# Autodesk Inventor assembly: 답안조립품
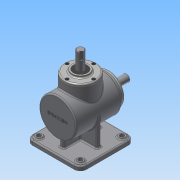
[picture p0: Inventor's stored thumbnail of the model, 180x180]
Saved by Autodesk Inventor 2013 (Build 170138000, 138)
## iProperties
Created: 2015-07
Part Number: 답안조립품
Document SubType Name: Assembly
Designer: Administrator
Author: Administrator
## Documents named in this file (14)
- C:\Users\Administrator\Desktop\450706V1016\답안조립품.iam
- C:\Users\Administrator\Desktop\450706V1016\본체.ipt
- C:\Users\Administrator\Desktop\450706V1016\M4.ipt
- C:\Users\Administrator\Desktop\450706V1016\메인 베벨기어.ipt
- C:\Users\Administrator\Desktop\450706V1016\메인 축.ipt
- 메인 축.ipt
- C:\Users\Administrator\Desktop\450706V1016\베어링 6203.ipt
- C:\Users\Administrator\Desktop\450706V1016\서브 베벨기어.ipt
- C:\Users\Administrator\Desktop\450706V1016\서브 축.ipt
- 서브 축.ipt
- C:\Users\Administrator\Desktop\450706V1016\오일실.ipt
- C:\Users\Administrator\Desktop\450706V1016\커버.ipt
- C:\Users\Administrator\Desktop\450706V1016\키 4x4.ipt
- C:\Users\Administrator\Desktop\450706V1016\키 5x5.ipt
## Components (8 placed, 1 different names)
1. M4:2
2. M4:3
3. M4:4
4. M4:5
5. M4:1
6. M4:6
7. M4:7
8. M4:8
